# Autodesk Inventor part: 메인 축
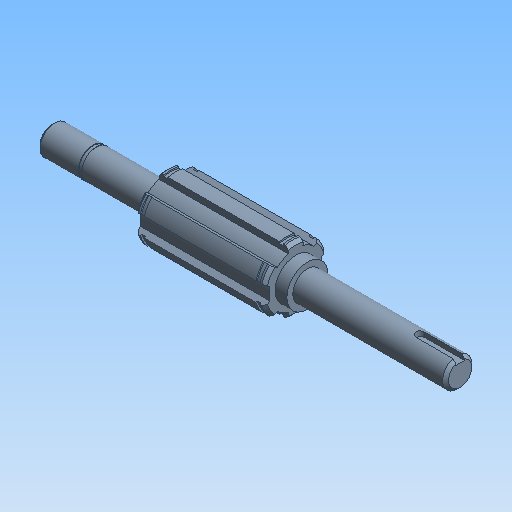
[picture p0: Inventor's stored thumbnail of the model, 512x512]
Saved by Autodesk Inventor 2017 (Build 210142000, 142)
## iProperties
Created: 2021-07
Part Number: 메인 축
Document SubType Name: 모델링
Designer: mdu
Mass: 168.567 g
Surface Area: 72.5108 cm^2
Volume: 21.4461 cm^3
Density: 7.86 g/cm^3
Material: 강철, 연강
Appearance: 연한 강청색
변환 표준: STEP AP214IS
파일 이름: C:\Users\SeoGD\Desktop\?쒗뿕\硫붿씤 異?.stp
전처리기: Build: 253, Release: 2010 SP1 - Date: Wed 07/29/2009
전송 단위: 밀리미터
불확실성: 0.01
Author: mdu
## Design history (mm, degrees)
sketch "스케치1"
  geometry: L1 (-69.5, 0)-(69.5, 0); L2 (69.5, 0)-(69.5, 5); L3 (69.5, 5)-(55.5, 5); L4 (55.5, 5)-(55.5, 4.8); L5 (55.5, 4.8)-(54.35, 4.8); L6 (54.35, 4.8)-(54.35, 5); L7 (54.35, 5)-(30.5, 5); L8 (30.5, 5)-(30.5, 9); L9 (30.5, 9)-(-13.5, 9); L10 (-13.5, 9)-(-13.5, 7); L11 (-13.5, 7)-(-17.5, 7); L12 (-17.5, 7)-(-17.5, 5); L13 (-17.5, 5)-(-69.5, 5); L14 (-69.5, 5)-(-69.5, 0); 2 further points
  constraints: 28 end point, 9 parallel, 4 collinear, 2 perpendicular, 1 coincident, 1 horizontal, 1 midpoint
  dimensions: "d2" = 1.15 distance between parallel lines of L6 L4; "d3" = 10 diameter of L3 L1; "d4" = 9.6 diameter of L5 L1; "d6" = 44 distance between parallel lines of L10 L8; "d7" = 4 distance between parallel lines of L12 L10; "d8" = 14 diameter of L11 L1; "d9" = 18 diameter of L9 L1; "d33" = 52 distance from line of L12.end L14; "d37" = 39 distance between parallel lines of L8 L2; "d38" = 14 distance between parallel lines of L2 L4
revolve "회전1" sketch "스케치1" stored, may be unused: angle "d10" = 90 deg
sketch "스케치2"
  geometry: L1 (2.5, 10.712)-(2.5, 8.646); L2 (-2.5, 10.712)-(-2.5, 8.646); A1 r 9 centre (0, 0) between (2.5, 8.646) and (-2.5, 8.646) reference; A2 r 11 centre (0, 0) between (2.5, 10.712) and (-2.5, 10.712); 1 further point
  constraints: 4 end point, 4 point on circle, 2 parallel, 1 centre point, 1 coincident, 1 vertical
  dimensions: "d11" = 22 diameter of A2; "d12" = 5 distance between parallel lines of L1 L2
extrude "돌출1" join sketch "스케치2" stored distance "d13" = 10; taper "d14" = 0 deg
chamfer "모따기1" distance "d15" = 1; stored, may be unused: second distance "d16" = 2, angle "d17" = 45 deg
node "작업 평면1"
node "작업 평면2"
sketch "스케치3"
  geometry: L1 (2.5, 10.712)-(2.5, 10.198); L2 (-2.5, 10.712)-(-2.5, 10.198); A1 r 11 centre (0, 0) between (2.5, 10.712) and (-2.5, 10.712) reference; A2 r 10.5 centre (0, 0) between (2.5, 10.198) and (-2.5, 10.198); 1 further point
  constraints: 4 end point, 2 point on circle, 1 centre point, 1 coincident, 1 parallel, 1 vertical
  dimensions: "d19" = 21 diameter of A2
extrude "돌출2" cut sketch "스케치3" distance "d20" = 1.35; taper "d21" = 0 deg
node "작업 평면3"
sketch "스케치4"
  geometry: L1 (-26, -5)-(-26, 5) reference; L2 (-26, 1.5)-(-12.5, 1.5); L3 (-12.5, -1.5)-(-26, -1.5); A1 r 1.5 centre (-12.5, 0) between (-12.5, -1.5) and (-12.5, 1.5); 2 further points
  constraints: 4 end point, 2 perpendicular, 2 point on circle, 2 point on line, 2 tangent, 1 centre point, 1 horizontal alignment, 1 midpoint
  dimensions: "d25" = 3 distance between parallel lines of L3 L2; "d26" = 15 dimension on A1 L1
extrude "돌출3" cut sketch "스케치4" distance "d27" = 1.8; taper "d28" = 0 deg
chamfer "모따기2" distance "d29" = 1; stored, may be unused: second distance "d30" = 2, angle "d31" = 45 deg
node "솔리드1"
node "솔리드 본체"
node "곡면 본체"
mirror "대칭1"
pattern_circular "원형 패턴1" dims "d23" = 360 deg
node "솔리드2"
other parameters: "d18" = -1.65
